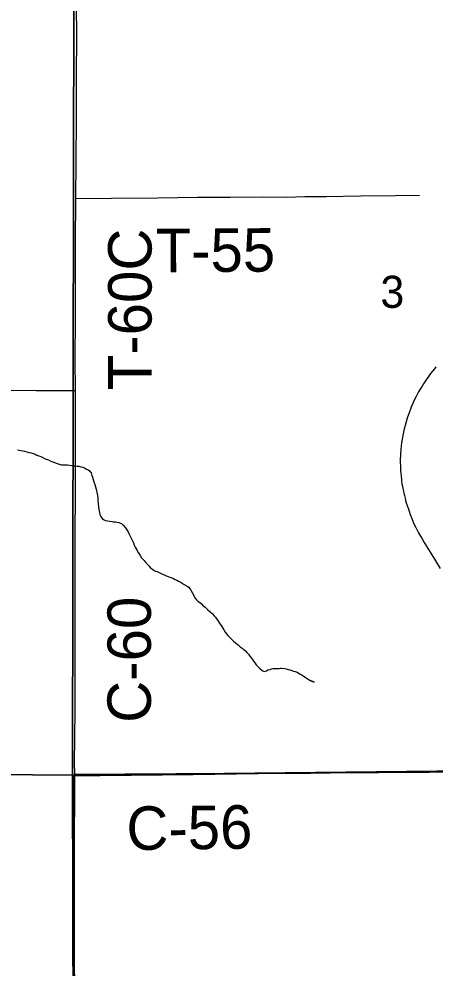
# Model space of a CAD drawing. Extents: x -17 to 88, y -5 to 22.
# Drawn here: x 5.65 to 6.195, y 18.897 to 20.136 of the extents above; entities that cross this region are included whole.
import ezdxf

# ---------------------------------------------------------------- set-up
doc = ezdxf.new("R2010")
doc.units = 0
for name, color, linetype in [('GM_X_County_Road', 7, 'Continuous'), ('GM_X_County_Road_Text', 7, 'Continuous'), ('GM_X_Interchange_Ramps', 7, 'Continuous'), ('GM_X_Minor_River', 7, 'Continuous'), ('GM_X_Section', 7, 'Continuous'), ('GM_X_Section_Text', 7, 'Continuous'), ('GM_X_Township', 7, 'Continuous'), ('GM_X_Township_Road', 7, 'Continuous'), ('GM_X_Township_Road_Text', 7, 'Continuous')]:
    doc.layers.add(name, color=color, linetype=linetype)

msp = doc.modelspace()

# ---------------------------------------------------------------- linework, layer by layer
at = {"layer": 'GM_X_County_Road'}
for points in [[(4.978, 19.6548), (5.0363, 19.6544), (5.0848, 19.6541), (5.1314, 19.6537), (5.1544, 19.6536), (5.1911, 19.6535), (5.2308, 19.6532), (5.2687, 19.6528), (5.3098, 19.6526), (5.3439, 19.6526), (5.3794, 19.6524), (5.4123, 19.652), (5.4583, 19.6518), (5.4757, 19.6516), (5.531, 19.6515), (5.5683, 19.6512), (5.6099, 19.6512), (5.6404, 19.651), (5.673, 19.6507), (5.7242, 19.6505)], [(5.7236, 19.148), (5.7233, 19.1666), (5.7236, 19.1946), (5.7238, 19.2362), (5.7239, 19.3456), (5.7239, 19.3879), (5.724, 19.4053), (5.7239, 19.4159), (5.7241, 19.4594), (5.7243, 19.5185), (5.7242, 19.5601), (5.7244, 19.6018), (5.7245, 19.6297), (5.7242, 19.6505)], [(5.7236, 19.148), (5.7565, 19.1479), (5.8781, 19.1494), (5.9633, 19.1505), (6.0316, 19.151), (6.0832, 19.1517), (6.1497, 19.1523), (6.1851, 19.1528), (6.2255, 19.1533)]]:
    msp.add_lwpolyline(points, dxfattribs=at)
at = {"layer": 'GM_X_Interchange_Ramps'}
msp.add_lwpolyline([(6.1956, 19.6813), (6.1936, 19.6789), (6.1911, 19.6759), (6.1887, 19.6729), (6.1867, 19.67), (6.185, 19.6676), (6.183, 19.6646), (6.1811, 19.6619), (6.1795, 19.6593), (6.1775, 19.6561), (6.1758, 19.6535), (6.1744, 19.6511), (6.1731, 19.6488), (6.1716, 19.6461), (6.1698, 19.6427), (6.1678, 19.6388), (6.1663, 19.6356), (6.1647, 19.6321), (6.1634, 19.629), (6.1624, 19.6262), (6.1611, 19.6229), (6.1598, 19.6191), (6.1581, 19.6143), (6.1567, 19.6097), (6.1554, 19.605), (6.1542, 19.6004), (6.1533, 19.5962), (6.1524, 19.5919), (6.1515, 19.5871), (6.1508, 19.5823), (6.1503, 19.5781), (6.1498, 19.5735), (6.1494, 19.5685), (6.1492, 19.5647), (6.1491, 19.5619), (6.149, 19.5591), (6.1491, 19.5558), (6.1492, 19.5529), (6.1493, 19.5502), (6.1494, 19.5467), (6.1497, 19.5428), (6.1501, 19.5383), (6.1505, 19.5347), (6.1508, 19.5323), (6.1513, 19.5289), (6.1519, 19.5255), (6.1525, 19.5225), (6.1532, 19.5192), (6.1537, 19.5166), (6.1545, 19.5134), (6.1553, 19.5101), (6.1561, 19.5069), (6.1569, 19.504), (6.158, 19.5004), (6.1592, 19.4969), (6.1605, 19.493), (6.162, 19.4885), (6.1641, 19.4833), (6.1655, 19.4801), (6.167, 19.4767), (6.169, 19.4725), (6.1712, 19.4682), (6.173, 19.4648), (6.1753, 19.4606), (6.1775, 19.4568), (6.1804, 19.4521), (6.1852, 19.4442), (6.1889, 19.4381), (6.2013, 19.4181)], dxfattribs=at)
at = {"layer": 'GM_X_Minor_River'}
for points in [[(5.6485, 19.5732), (5.6579, 19.5715), (5.6606, 19.5707), (5.6636, 19.5695), (5.6663, 19.569), (5.6689, 19.5682), (5.6716, 19.5674), (5.6738, 19.5662)], [(5.6738, 19.5662), (5.6765, 19.5654), (5.6791, 19.5643), (5.6817, 19.5631), (5.6848, 19.5615), (5.6889, 19.5599), (5.6923, 19.5583), (5.6961, 19.5571), (5.6991, 19.5559), (5.7017, 19.5547), (5.7044, 19.5539), (5.7063, 19.5535), (5.7082, 19.5535), (5.7116, 19.5534), (5.7139, 19.5534), (5.7165, 19.5529), (5.7196, 19.5525), (5.7218, 19.5524), (5.7241, 19.5524), (5.7268, 19.552), (5.7287, 19.5516), (5.7313, 19.5511), (5.734, 19.5503), (5.7362, 19.5495), (5.7381, 19.5483), (5.7408, 19.5472), (5.7426, 19.5456), (5.7449, 19.5429), (5.7459, 19.5395), (5.7467, 19.5376), (5.7474, 19.5345), (5.7484, 19.5314), (5.7495, 19.528), (5.7506, 19.525), (5.7513, 19.5219), (5.7527, 19.5158), (5.753, 19.5135), (5.7534, 19.5105), (5.7537, 19.507), (5.754, 19.5029), (5.7547, 19.4987), (5.755, 19.4956), (5.7553, 19.4933), (5.7557, 19.4911), (5.7564, 19.4888), (5.7575, 19.4861), (5.7593, 19.4834), (5.7612, 19.4822), (5.7635, 19.481), (5.7661, 19.4806), (5.7692, 19.4802), (5.7722, 19.4797), (5.7741, 19.4793), (5.7767, 19.4789), (5.7786, 19.4785), (5.7809, 19.4781), (5.7832, 19.4773), (5.785, 19.4765), (5.7869, 19.4749), (5.7899, 19.4711), (5.7917, 19.4687), (5.7932, 19.4661), (5.7943, 19.4638), (5.7954, 19.4611), (5.7969, 19.4588), (5.798, 19.4561), (5.7991, 19.4542), (5.8002, 19.4519), (5.8009, 19.4488), (5.8023, 19.4461), (5.8038, 19.4438), (5.8049, 19.4419), (5.806, 19.4396), (5.8075, 19.4373), (5.809, 19.435), (5.8108, 19.4323), (5.8142, 19.4288), (5.8157, 19.4269), (5.8205, 19.4215), (5.822, 19.4196), (5.8239, 19.418), (5.8273, 19.4157), (5.8291, 19.4149), (5.831, 19.4141), (5.8337, 19.4129), (5.8363, 19.4117), (5.8393, 19.4105), (5.8423, 19.4089), (5.8454, 19.4078), (5.8476, 19.407), (5.8495, 19.4065), (5.8525, 19.405), (5.8548, 19.4038), (5.8567, 19.403), (5.8589, 19.4018), (5.8612, 19.4006), (5.8638, 19.3991), (5.8664, 19.3975), (5.8702, 19.3951), (5.8725, 19.3936), (5.8739, 19.3917)], [(5.8739, 19.3917), (5.8754, 19.3897), (5.8769, 19.3867), (5.8787, 19.384), (5.8806, 19.3801), (5.8828, 19.3771), (5.885, 19.3751), (5.8869, 19.3736), (5.8888, 19.3724), (5.8906, 19.3701), (5.894, 19.3677), (5.897, 19.3646), (5.9004, 19.3615), (5.9034, 19.3588), (5.9056, 19.3565), (5.9075, 19.3546), (5.9089, 19.3523), (5.9104, 19.3503), (5.9119, 19.348), (5.9134, 19.3454), (5.9156, 19.3423), (5.9182, 19.338), (5.92, 19.335), (5.9219, 19.3327), (5.9237, 19.3307), (5.9252, 19.3288), (5.9312, 19.3234), (5.9335, 19.3211), (5.9357, 19.3195), (5.9376, 19.3179), (5.9398, 19.316), (5.9424, 19.3141), (5.9443, 19.3125), (5.9466, 19.3106), (5.9484, 19.3086), (5.9507, 19.3063), (5.9525, 19.3036), (5.9544, 19.3013), (5.9559, 19.2994), (5.9573, 19.2971), (5.9588, 19.2951), (5.9607, 19.2925), (5.9637, 19.2894), (5.9655, 19.2878), (5.9685, 19.2851), (5.9712, 19.2839), (5.9742, 19.2846), (5.9761, 19.2857), (5.9788, 19.2864), (5.9807, 19.2871), (5.983, 19.2875), (5.9853, 19.2874), (5.988, 19.2878), (5.9906, 19.2877), (5.9925, 19.2881), (5.9944, 19.288), (5.9978, 19.2876), (5.9997, 19.2872), (6.0024, 19.2864), (6.0046, 19.2859), (6.0073, 19.2851), (6.0096, 19.2843), (6.0118, 19.2835), (6.0141, 19.2827), (6.0164, 19.2815), (6.0182, 19.2804), (6.0205, 19.2792), (6.0224, 19.2776), (6.0246, 19.2761), (6.0299, 19.2729), (6.0314, 19.2721), (6.0363, 19.2698), (6.0318, 19.2718), (6.0363, 19.2698)]]:
    msp.add_lwpolyline(points, dxfattribs=at)
at = {"layer": 'GM_X_Section'}
for points in [[(5.7223, 20.1762), (5.7206, 19.1483), (4.7297, 19.1567), (4.7146, 20.1753)], [(6.7146, 20.1751), (6.7133, 19.1594), (5.7206, 19.1483), (5.7223, 20.1762)], [(6.7133, 19.1594), (6.7087, 18.155), (5.7233, 18.1499), (5.7206, 19.1483)], [(4.7297, 19.1567), (5.7206, 19.1483), (5.7233, 18.1499), (4.7287, 18.1546)]]:
    msp.add_lwpolyline(points, close=True, dxfattribs=at)
at = {"layer": 'GM_X_Township'}
for points in [[(5.0464, 18.1513), (5.7149, 18.1469), (5.7215, 18.6472), (5.7225, 19.1491), (6.2534, 19.1527), (6.9691, 19.1558), (7.2261, 19.1535), (7.7361, 19.149), (8.236, 19.1446), (8.7331, 19.1436), (8.7348, 19.4138), (8.7274, 19.89), (8.7281, 20.1646), (7.7177, 20.1665), (7.7206, 20.6696), (7.7218, 20.9)], [(8.709, 14.1), (8.7164, 14.7728), (8.7243, 15.8906), (8.7261, 16.1499), (8.7273, 16.2993), (8.7317, 17.1395), (8.7241, 18.1383), (8.7331, 19.1436), (8.236, 19.1446), (7.7361, 19.149), (7.2261, 19.1535), (6.9691, 19.1558), (6.2534, 19.1527), (5.7225, 19.1491), (5.7215, 18.6472), (5.7149, 18.1469), (5.0464, 18.1513)]]:
    msp.add_lwpolyline(points, dxfattribs=at)
at = {"layer": 'GM_X_Township_Road'}
for points in [[(5.7249, 19.9013), (5.7254, 19.9491), (5.7255, 20.0068), (5.7256, 20.0546), (5.726, 20.1192), (5.7256, 20.1478), (5.7257, 20.1543), (5.7251, 20.1636), (5.7247, 20.1683), (5.724, 20.1726)], [(5.7242, 19.6505), (5.7241, 19.6907), (5.7242, 19.7453), (5.7245, 19.8429), (5.7249, 19.9013)], [(5.7249, 19.9013), (5.7714, 19.9017), (5.8322, 19.9023), (5.8844, 19.9029), (5.9267, 19.9032), (5.9708, 19.9033), (6.0006, 19.9032), (6.0242, 19.9037), (6.0522, 19.9041), (6.0969, 19.9047), (6.1429, 19.9054), (6.1741, 19.9055)], [(5.7221, 18.6508), (5.7228, 18.7218), (5.7233, 18.7956), (5.7235, 18.8598), (5.7231, 18.9169), (5.7232, 18.9716), (5.7231, 19.0627), (5.7235, 19.1248), (5.7236, 19.148)]]:
    msp.add_lwpolyline(points, dxfattribs=at)

# ---------------------------------------------------------------- texts
at = {"layer": 'GM_X_County_Road_Text'}
for s, rotation, p in [('C-60', 90, (5.823, 19.2167)), ('C-56', 0.6858, (5.7913, 19.0505))]:
    msp.add_text(s, height=0.05682, rotation=rotation, dxfattribs=at).set_placement(p)
at = {"layer": 'GM_X_Section_Text'}
msp.add_text('3', height=0.0419, rotation=0, dxfattribs=at).set_placement((6.1231, 19.7585))
at = {"layer": 'GM_X_Township_Road_Text'}
for s, rotation, p in [('T-60C', 90, (5.8239, 19.6509)), ('T-55', 0.3526, (5.8294, 19.8049))]:
    msp.add_text(s, height=0.05682, rotation=rotation, dxfattribs=at).set_placement(p)

doc.saveas('drawing.dxf')
